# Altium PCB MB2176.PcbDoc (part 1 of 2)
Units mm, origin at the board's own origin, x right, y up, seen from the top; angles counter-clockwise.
Board outline 43 x 47 mm, 2 copper layers (Top Layer, Bottom Layer), stack 0.996 mm thick; 80 components, 70 nets, 345 pads, 549 vias.
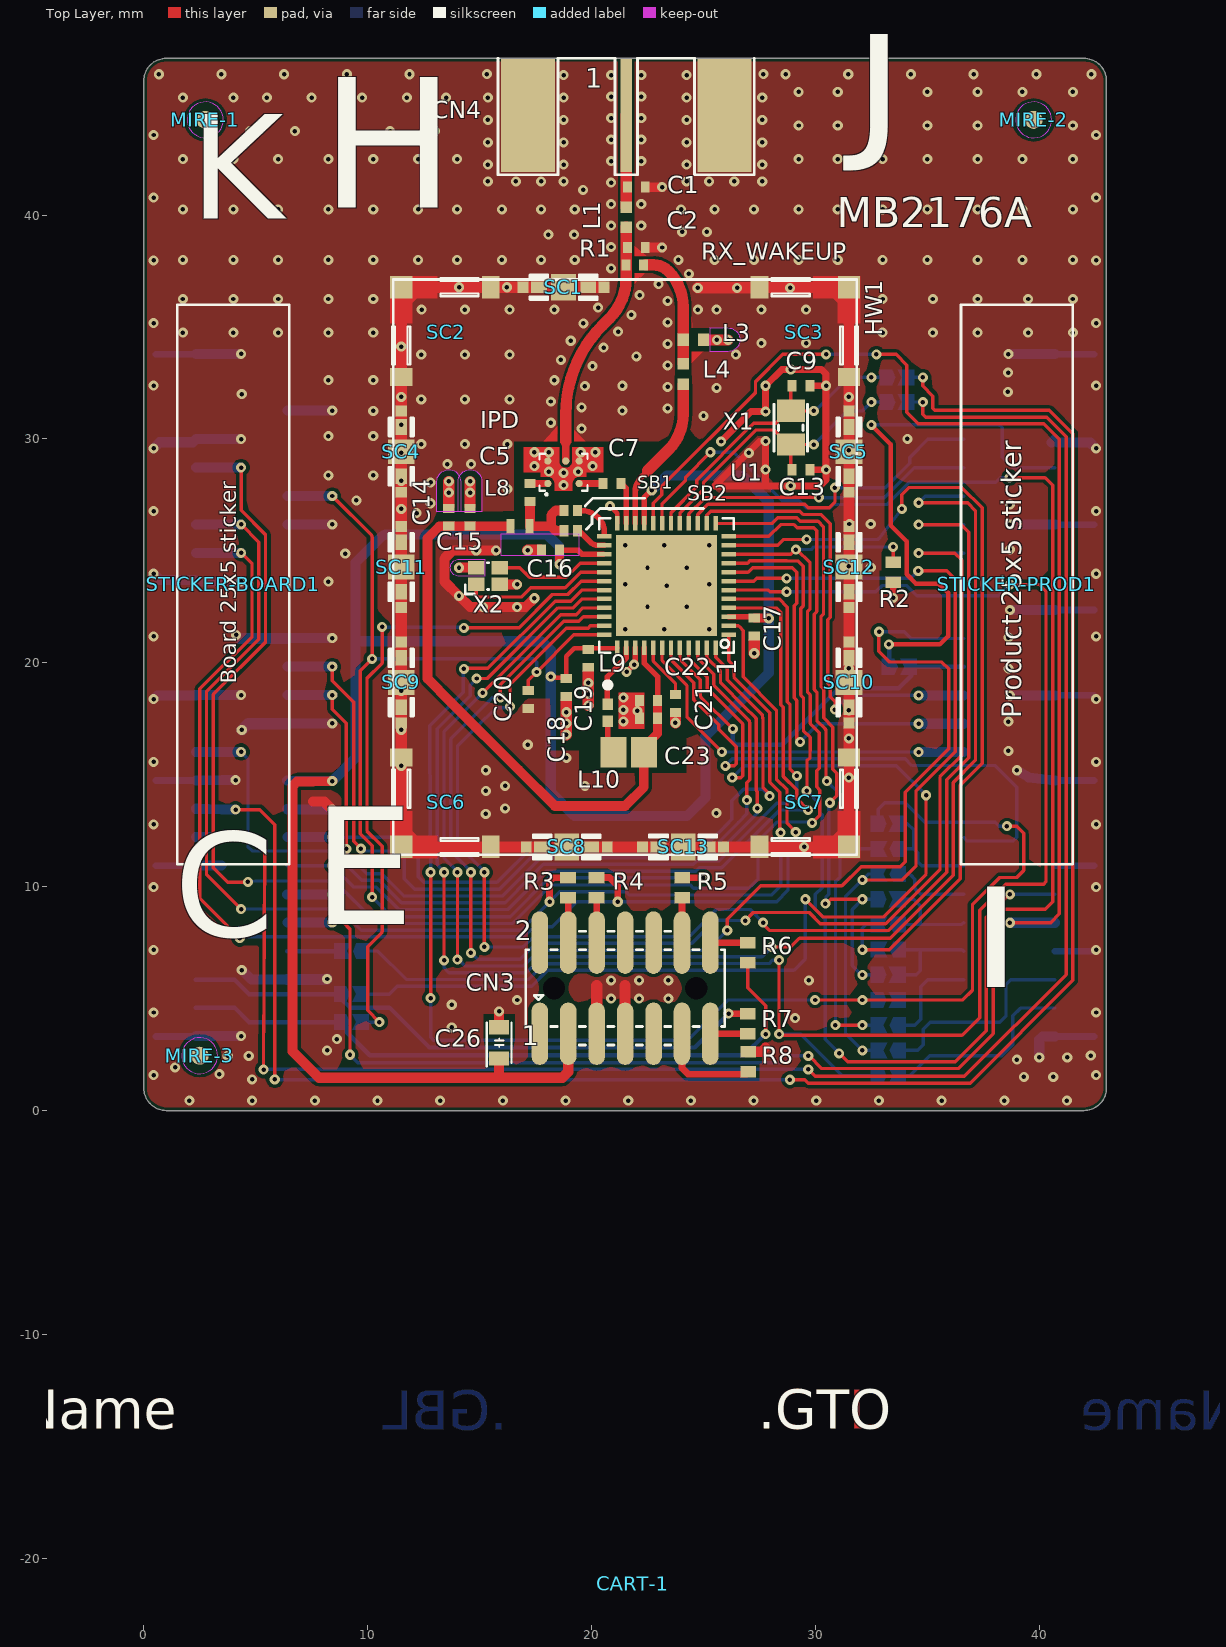
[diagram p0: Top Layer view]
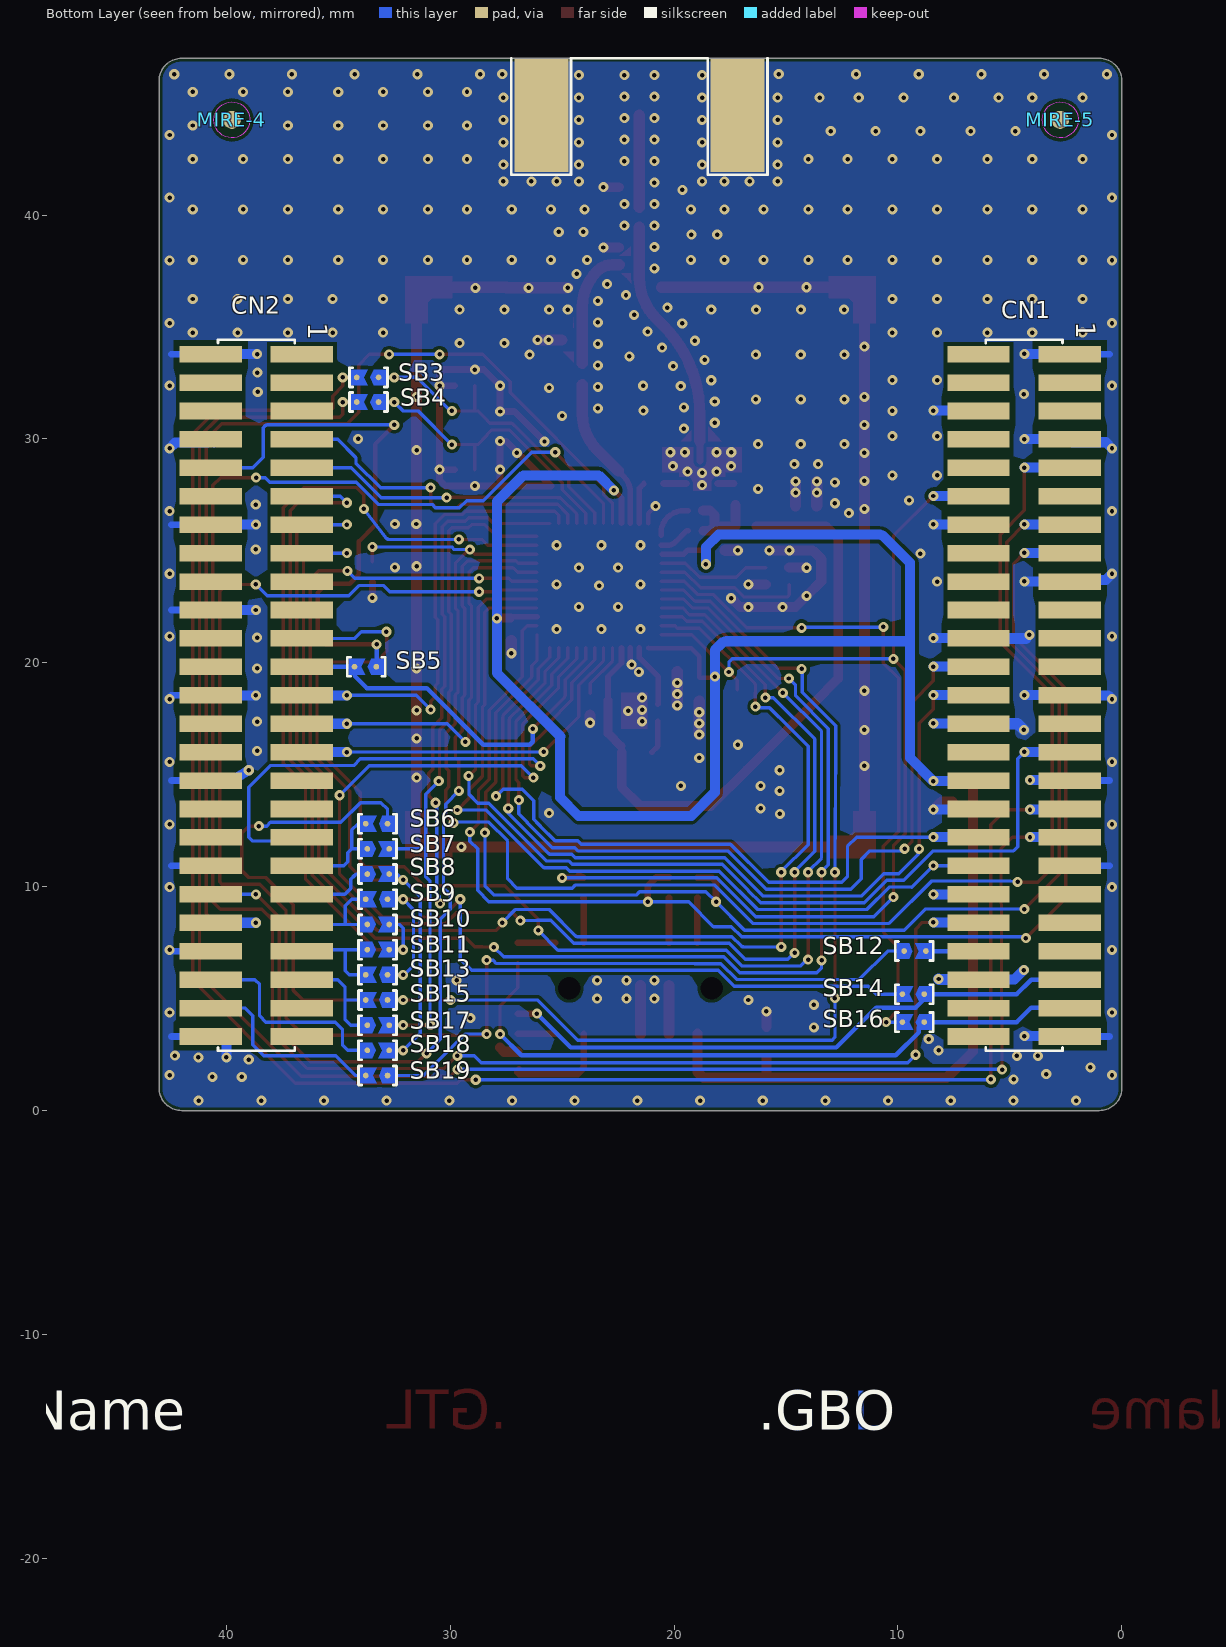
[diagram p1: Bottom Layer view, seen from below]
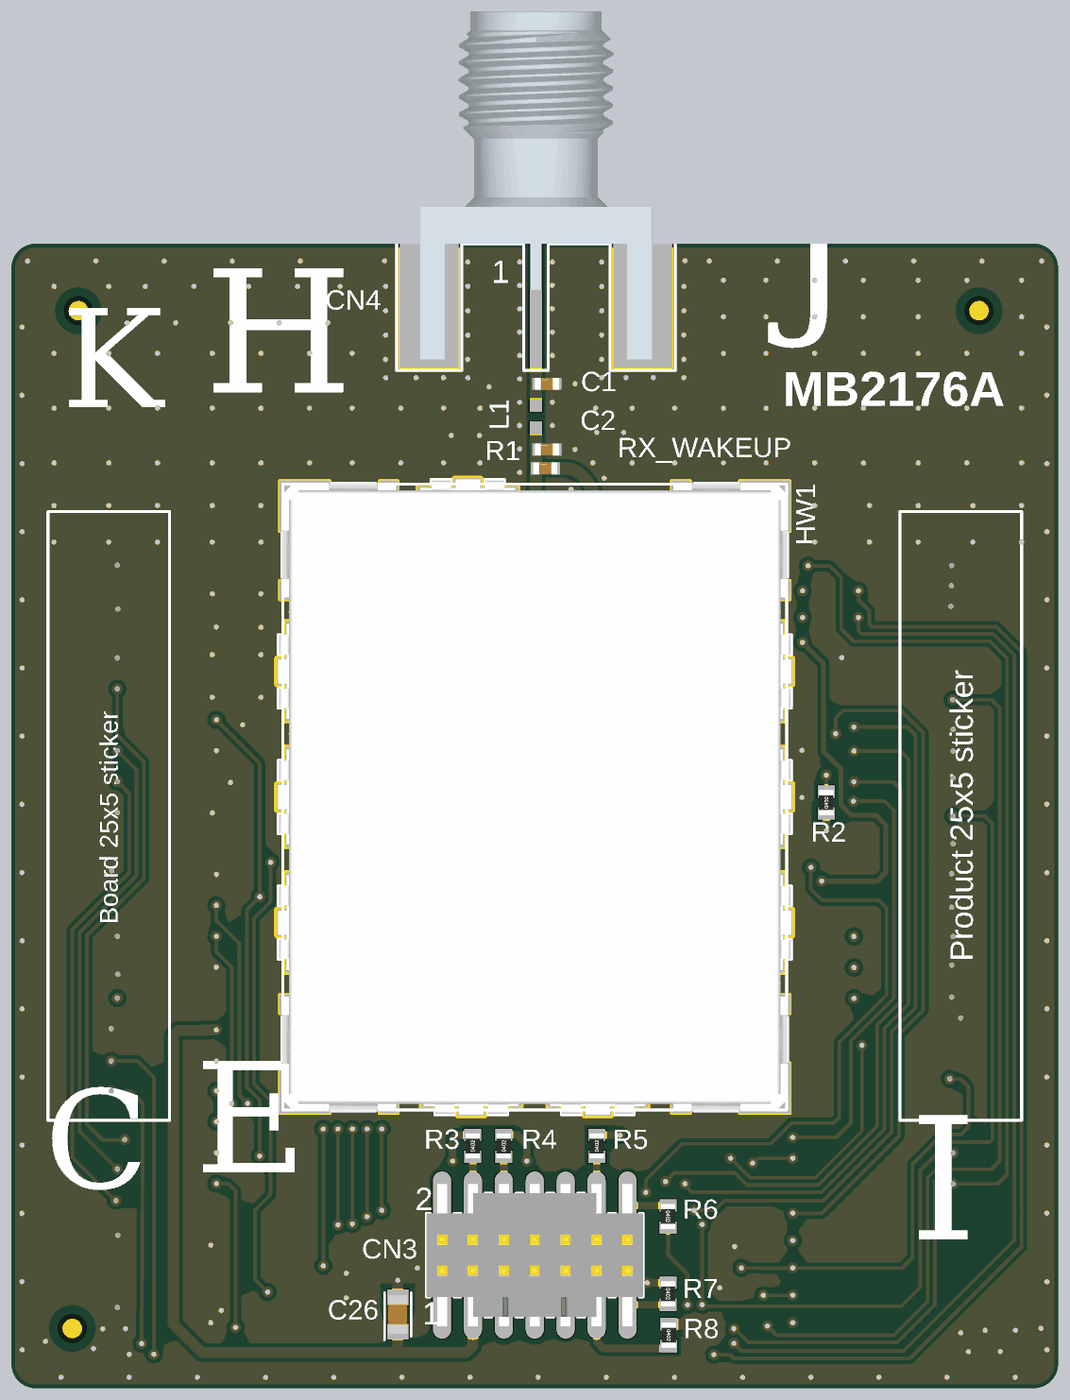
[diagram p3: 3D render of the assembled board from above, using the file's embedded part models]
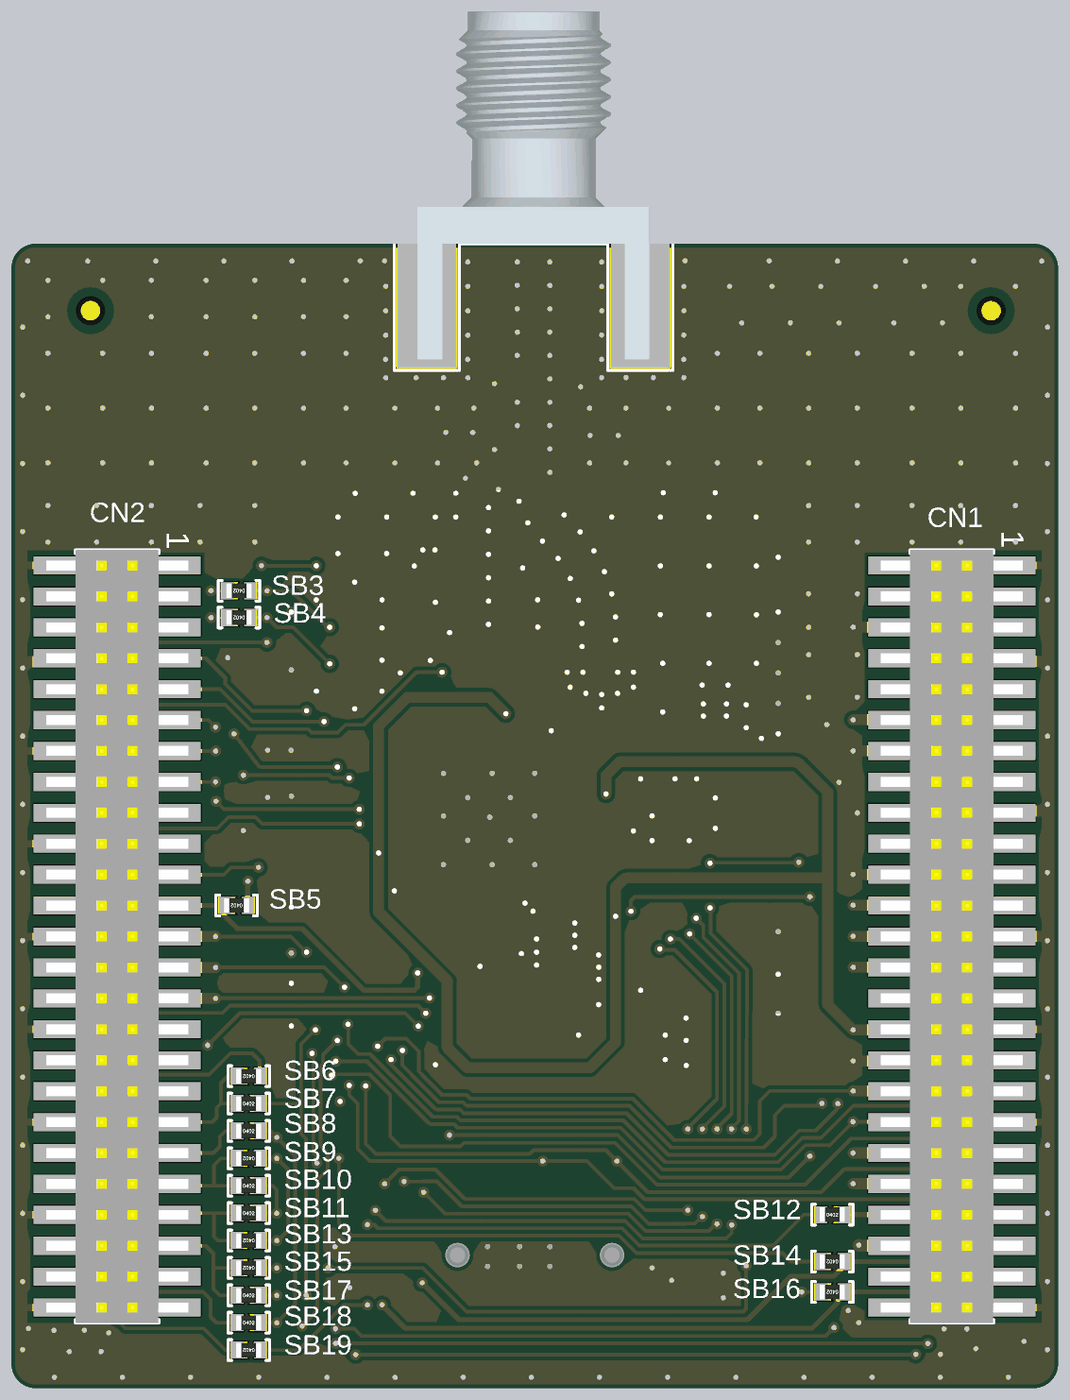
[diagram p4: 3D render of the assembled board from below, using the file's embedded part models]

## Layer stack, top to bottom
Top Solder: solder mask 0.0102, Solder Resist, Dk 3.5
Top Layer: signal copper 0.0406
Dielectric 2: core 0.9144, FR4, Dk 4.3
Bottom Layer: signal copper 0.0406
Bottom Solder: solder mask 0.0102, Solder Resist, Dk 3.5

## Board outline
0,1 ccw(c1,1) 1,0 42,0 ccw(c42,1) 43,1 43,46 ccw(c42,46) 42,47 1,47 ccw(c1,46) 0,46

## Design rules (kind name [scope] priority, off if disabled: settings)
BoardOutlineClearance [All] p1: gap=0.14 ignorepadtopadclearanceinfootprint=FALSE
Clearance [touchesRoom('RoomDefinition_3')] p1: gap=0.095 ignorepadtopadclearanceinfootprint=FALSE
Clearance Clearance_Keepout [All vs IsKeepOut] p2: gap=0.15 ignorepadtopadclearanceinfootprint=TRUE except(0: Poly-Region)
Clearance Clearance_IPD [InPadClass('IPD_PAD')] p3: gap=0.14 ignorepadtopadclearanceinfootprint=FALSE
Clearance Clearance_RF-50R [InNetClass('NC_RF-50R')] p4: gap=0.118 ignorepadtopadclearanceinfootprint=FALSE
Clearance Clearance_Default_Same-net_GND [InNet('GND')] p5: gap=0.15 ignorepadtopadclearanceinfootprint=TRUE except(0: SMDPad-Via SMDPad-Hole Via-Via Via-Region; 0.1: Arc-SMDPad Track-SMDPad Via-Hole; 0.12: SMDPad-SMDPad)
Clearance Clearance_Default_Same-net [All] p6: gap=0.15 ignorepadtopadclearanceinfootprint=TRUE except(0.1: Via-Via; 0.12: Arc-SMDPad Track-SMDPad SMDPad-SMDPad)
Clearance Clearance_Default [All] p7: gap=0.15 ignorepadtopadclearanceinfootprint=FALSE except(0.1: Arc-Via Track-Via)
ComponentClearance [All] p1: gap=0.165 collisioncheckmode=3 verticalgap=0.165 showdistances=FALSE
HoleSize [All] p1: absolutevalues=TRUE maxlimit=10 minlimit=0.025 maxpercent=80.000 minpercent=20.000
MinimumSolderMaskSliver [All] p1: minsoldermaskwidth=0.1
PlaneConnect [All] p1: planeconnectstyle=Relief reliefexpansion=0.508 reliefentries=4 reliefconductorwidth=0.21 reliefairgap=0.21
PolygonConnect PolygonConnect_CLIP [TouchesRoom('RoomDefinition')or TouchesRoom('RoomDefinition_1') or   TouchesRoom('RoomDefinition_2')  or TouchesRoom('RoomDefinition_4')  or TouchesRoom('RoomDefinition_5')    or TouchesRoom('RoomDefinition_6')] p1: connectstyle=Direct reliefconductorwidth=0.3 reliefentries=4 polygonreliefangle="90 Angle" airgapwidth=0.25
PolygonConnect PolygonConnect_Default_1 [All] p2: thpad.connectstyle=Relief thpad.reliefconductorwidth=0.3 thpad.reliefentries=4 thpad.polygonreliefangle="90 Angle" thpad.airgapwidth=0.25 smdpad.connectstyle=NoConnect smdpad.reliefconductorwidth=0.254 smdpad.reliefentries=4 smdpad.polygonreliefangle="90 Angle" smdpad.airgapwidth=0.254 via.connectstyle=Direct via.reliefconductorwidth=0.254 via.reliefentries=4 via.polygonreliefangle="90 Angle" via.airgapwidth=0.254
RoomDefinition RoomDefinition_6 [False vs False] p1: confinementstyle=ConfineIn formatcopy=TRUE lockcomponents=FALSE outline 22.217,41.754 23.136,41.754 23.136,38.308 22.217,38.308
RoomDefinition RoomDefinition_5 [False vs False] p2: confinementstyle=ConfineIn formatcopy=TRUE lockcomponents=FALSE outline 7.053,14.176 7.972,14.176 7.972,12.975 7.053,12.975
RoomDefinition RoomDefinition_4 [False vs False] p3: confinementstyle=ConfineIn formatcopy=TRUE lockcomponents=FALSE outline 16.668,18.313 18.139,18.313 18.139,17.066 16.668,17.066
RoomDefinition RoomDefinition_3 [All] p4: confinementstyle=ConfineOut formatcopy=TRUE lockcomponents=FALSE outline 17.724,29.336 19.774,29.336 19.774,27.744 17.724,27.744
RoomDefinition RoomDefinition_2 [False] p5: confinementstyle=ConfineIn formatcopy=TRUE lockcomponents=FALSE outline 27.072,12.919 27.072,10.495 16.087,10.495 16.087,12.919
RoomDefinition RoomDefinition_1 [False] p6: confinementstyle=ConfineIn formatcopy=TRUE lockcomponents=FALSE outline 32.674,15.775 30.25,15.775 30.25,28.309 32.674,28.309
RoomDefinition [False] p7: confinementstyle=ConfineIn formatcopy=TRUE lockcomponents=FALSE outline 12.674,16.465 10.25,16.465 10.25,27.45 12.674,27.45
RoutingVias RoutingVias_Default [All] p1: holewidth=0.3 width=0.6 viastyle="Through Hole" minholewidth=0.3 minwidth=0.6 maxholewidth=0.3 maxwidth=0.6 useviatemplates=TRUE viatemplateguid#1={7280008E-C29C-4D1A-93D7-D7784B042BC4} viatemplatename#1=v45h20m0mx0
SilkToSilkClearance [All] p1 off: silktosilkclearance=0.2
SilkToSolderMaskClearance [IsPad] p1 off: minsilkscreentomaskgap=0.2 clearancetoexposedcopper=TRUE
SolderMaskExpansion [All] p1: expansion=0.102 istentingtop=FALSE
ViasUnderSMD [InPadClass('PC__VIAS-IN-PAD')] p1: allowed=TRUE
Width Width_RF-50R [InNetClass('NC_RF-50R')] p1: maxlimit=0.55 minlimit=0.25 preferedwidth=0.51 impedanceprofiledriven=TRUE impedanceprofileid={AD1550EC-3D0E-4E34-9E21-FD44D1EEEC04} impedanceprofilevalue=50.000000 minimp=50.000000 maximp=50.000000 favimp=50.000000
Width Width_Default [All] p2: maxlimit=10 minlimit=0.15 preferedwidth=0.2
24 further rules are at their usual default settings.

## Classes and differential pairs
net class IPD: NetC5_1 NetC7_2
pad class PC__VIAS-IN-PAD: U1-49
net class NC_RF-50R: NetC1_2 NetC2_2 NetL3_1

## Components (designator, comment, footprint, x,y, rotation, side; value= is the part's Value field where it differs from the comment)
C1 "Capacitor" GRM155--GJM155-0_05-MFG 22,41.25 r180 top value=TBD
C2 "Capacitor" GRM155--GJM155-0_05-MFG 22,38.55 r180 top value=TBD
C5 "Capacitor" GRM155--GJM155-0_05-MFG 17.258,27.611 r90 top value=100pF
C7 "Capacitor" GRM155--GJM155-0_05-MFG 20.909,28.008 r180 top value=100pF
C9 "Capacitor" GRM155--GJM155-0_05-MFG 29.35,32.375 r180 top value=6.8pF
C13 "Capacitor" GRM155--GJM155-0_05-MFG 29.35,28.625 r180 top value=6.8pF
C14 "Capacitor" GRM155--GJM155-0_05-MFG 13.625,26.5 r90 top value=100pF
C15 "Capacitor" GRM155--GJM155-0_05-MFG 14.575,26.5 r270 top value=100nF
C16 "Capacitor" GRM155--GJM155-0_05-MFG 18.175,25.025 r0 top value=100nF
C17 "Capacitor" GRM155--GJM155-0_05-MFG 27.27,21.6 r90 top value=100nF
C18 "Capacitor" GRM155--GJM155-0_05-MFG 18.875,18.889 r90 top value=4.7uF
C19 "Capacitor" GRM155--GJM155-0_05-MFG 19.857,20.2 r90 top value=TBD
C20 "Capacitor" GRM155--GJM155-0_05-MFG 17.172,18.352 r90 top value=100nF
C21 "Capacitor" GRM155--GJM155-0_05-MFG 23.75,18.175 r90 top value=220nF
C22 "Capacitor" GRM155--GJM155-0_05-MFG 22.55,18.321 r0 top value=4.7uF
C23 "Capacitor" GRM155--GJM155-0_05-MFG 22.55,17.525 r180 top value=100nF
C26 "Capacitor" C0603 15.875,3.025 r270 top value=1uF
CART-1 "Comment" Sheetbox_4L2S -23.25,-26.5 r0 top
CN1 "FTSH-125-02-L-DV" CON_SAMTEC_FTSH-125-02-L-DV_INV 4.366,18.548 r270 bottom locked value="Header 25x2"
CN2 "FTSH-125-02-L-DV" CON_SAMTEC_FTSH-125-02-L-DV_INV 38.656,18.548 r270 bottom locked value="Header 25x2"
CN3 "Header 7x2" CON_SAMTEC_FTSH-107-01-L-DV-K-A 21.5,5.465 r0 top locked
CN4 "mmcx" CON_SMA-RF_CINCH_142-0701-851 21.55,47 r0 top
HW1 "S02-20150300" SHIELD_HARWIN_S02-25200300_20X25_H3 21.5,24.275 r0 top locked value=S02-25200300R
IPD "STM32WL33_IPD" STM32WL33_IPD 19.674,27.786 r90 top
L1 "Inductor" L0402#1 21.55,39.9 r90 top value=0R
L3 "Inductor" L0402#2 24.55,34.425 r0 top value=TBD
L4 "Inductor" L0402#1 24.1,32.9 r90 top value=TBD
L8 "Inductor" LQW15AN_00-W0_6-0_1-MFG 16.8,26.1 r0 top value=TBD
L9 "Inductor" LQG15HH_02-IPC_C 20.725,17.773 r270 top value=TBD
L10 "Inductor" LQM21FN_70-IPC_C 21.663,16.008 r180 top value=10µH
MIRE-1 "Comment" MIRE_PLACE_SMD_0P8MM 2.75,44.25 r0 top
MIRE-2 "Comment" MIRE_PLACE_SMD_0P8MM 39.75,44.25 r0 top
MIRE-3 "Comment" MIRE_PLACE_SMD_0P8MM 2.5,2.45 r0 top
MIRE-4 "Comment" MIRE_PLACE_SMD_0P8MM 39.75,44.25 r180 bottom
MIRE-5 "Comment" MIRE_PLACE_SMD_0P8MM 2.75,44.25 r180 bottom
R1 "Resistor" GRM155--GJM155-0_05-MFG 21.93,37.775 r180 top value=0
R2 "Resistor" R0402 33.475,24.05 r90 top value=100K
R3 "Resistor" R0402 18.95,9.95 r90 top value=47R
R4 "Resistor" R0402 20.225,9.95 r90 top value=47R
R5 "Resistor" R0402 24.05,9.95 r90 top value=47R
R6 "Resistor" R0402 26.975,7.05 r270 top value=47R
R7 "Resistor" R0402 26.975,3.875 r270 top value=47R
R8 "Resistor" R0402 27.003,2.175 r270 top value=47R
SB1 "SB_ON" SOLDER-BRIDGE_R0201_0R 19.075,26.8 r180 top value=0R
SB2 "SB_ON" SOLDER-BRIDGE_R0201_0R 19.075,25.9 r180 top value=0R
SB3 "SB_ON" SOLDER-BRIDGE_R0402-0R 33.65,32.747 r0 bottom
SB4 "SB_ON" SOLDER-BRIDGE_R0402-0R 33.65,31.647 r0 bottom
SB5 "SB_ON" SOLDER-BRIDGE_R0402-0R 33.75,19.825 r0 bottom
SB6 "SB_ON" SOLDER-BRIDGE_R0402-0R 33.25,12.812 r0 bottom
SB7 "SB_ON" SOLDER-BRIDGE_R0402-0R 33.25,11.688 r180 bottom
SB8 "SB_ON" SOLDER-BRIDGE_R0402-0R 33.25,10.563 r180 bottom
SB9 "SB_ON" SOLDER-BRIDGE_R0402-0R 33.25,9.437 r0 bottom
SB10 "SB_ON" SOLDER-BRIDGE_R0402-0R 33.25,8.313 r180 bottom
SB11 "SB_ON" SOLDER-BRIDGE_R0402-0R 33.25,7.187 r180 bottom
SB12 "SB_ON" SOLDER-BRIDGE_R0402-0R 9.275,7.125 r180 bottom
SB13 "SB_ON" SOLDER-BRIDGE_R0402-0R 33.25,6.062 r0 bottom
SB14 "SB_ON" SOLDER-BRIDGE_R0402-0R 9.275,5.2 r0 bottom
SB15 "SB_ON" SOLDER-BRIDGE_R0402-0R 33.25,4.938 r0 bottom
SB16 "SB_ON" SOLDER-BRIDGE_R0402-0R 9.275,3.95 r0 bottom
SB17 "SB_ON" SOLDER-BRIDGE_R0402-0R 33.25,3.812 r180 bottom
SB18 "SB_ON" SOLDER-BRIDGE_R0402-0R 33.25,2.688 r180 bottom
SB19 "SB_ON" SOLDER-BRIDGE_R0402-0R 33.25,1.562 r0 bottom
SC1 "Shield-clip_S0951-46R" CLIP_HARWIN_S0951-46R 18.75,36.775 r180 top value=S0951-46R
SC2 "Shield-clip_S0951-46R" CLIP_HARWIN_S0981-46R 11.5,36.775 r180 top value=S0981-46R
SC3 "Shield-clip_S0951-46R" CLIP_HARWIN_S0981-46R 31.5,36.775 r90 top value=S0981-46R
SC4 "Shield-clip_S0951-46R" CLIP_HARWIN_S0951-46R 11.5,29.433 r90 top value=S0951-46R
SC5 "Shield-clip_S0951-46R" CLIP_HARWIN_S0951-46R 31.5,29.433 r90 top value=S0951-46R
SC6 "Shield-clip_S0951-46R" CLIP_HARWIN_S0981-46R 11.5,11.775 r270 top value=S0981-46R
SC7 "Shield-clip_S0951-46R" CLIP_HARWIN_S0981-46R 31.5,11.775 r0 top value=S0981-46R
SC8 "Shield-clip_S0951-46R" CLIP_HARWIN_S0951-46R 18.89,11.774 r180 top value=S0951-46R
SC9 "Shield-clip_S0951-46R" CLIP_HARWIN_S0951-46R 11.5,19.12 r90 top value=S0951-46R
SC10 "Shield-clip_S0951-46R" CLIP_HARWIN_S0951-46R 31.5,19.12 r270 top value=S0951-46R
SC11 "Shield-clip_S0951-46R" CLIP_HARWIN_S0951-46R 11.5,24.278 r90 top value=S0951-46R
SC12 "Shield-clip_S0951-46R" CLIP_HARWIN_S0951-46R 31.5,24.278 r270 top value=S0951-46R
SC13 "Shield-clip_S0951-46R" CLIP_HARWIN_S0951-46R 24.09,11.775 r0 top value=S0951-46R
STICKER-BOARD1 "Comment" STICKER_BOARD_25X5 4,23.5 r90 top
STICKER-PROD1 "Comment" STICKER_PRODUCT_25X5 39,23.5 r90 top
U1 "STM32WL33" ICC_QFN48-EPAD-4P5X4P5_6X6_P040 23.35,23.45 r180 top
X1 "XTAL_2_PINS" CRY_NX2012SA_2P 28.9,30.5 r90 top value=32.768kHz
X2 "XTAL_4_PINS" CRY_NX1612SA_4P 15.38,23.875 r0 top locked value=48MHz

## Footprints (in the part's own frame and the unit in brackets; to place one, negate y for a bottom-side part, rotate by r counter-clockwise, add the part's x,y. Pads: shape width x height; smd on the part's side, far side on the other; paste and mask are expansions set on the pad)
C0603 [mm]
  rect 0.64x0.89 smd mask+0.05: 1(-0.7,0) 2(0.7,0)
  silkscreen extent -0.9,-0.55 1.05,0.55, body extent -0.9,-0.5 0.9,0.5, height 1.4
CLIP_HARWIN_S0951-46R [mm] "MCD-01587_CLIP-X1"
  rect 0.48x0.5 smd mask+0.1: 1(-1.81,0) 1(1.81,0)
  rect 0.7x0.5 smd mask+0.1: 1(-1.1,0) 1(1.1,0)
  rect 1.1x1.2 smd mask+0.1: 1(0,0)
  silkscreen extent -1.5,-0.55 1.5,0.55, body extent -2.05,-0.65 2.05,0.65, height 1.28
CLIP_HARWIN_S0981-46R [mm] "MCD-02164"
  rect 0.8x1 smd mask+0.05: 1(-4,0)
  rect 1x0.8 smd mask+0.05: 1(0,4)
  rect 1x1 smd mask+0.05: 1(0,0)
  Top Layer region: -1.6,-0.5 0.5,-0.5 0.5,1.6 -0.5,1.6 -0.5,0.7 -0.7,0.5 -1.6,0.5
  silkscreen extent -3.45,-0.4 0.4,3.45, body extent -4.3,-0.46 0.46,4.3, height 1.4
CON_SAMTEC_FTSH-107-01-L-DV-K-A [mm] "MCD-01959"
  oval 0.74x2.79 smd mask+0.05: 1(-3.81,-2.035) 2(-3.81,2.035) 3(-2.54,-2.035) 4(-2.54,2.035) 5(-1.27,-2.035) 6(-1.27,2.035) 7(0,-2.035) 8(0,2.035) 9(1.27,-2.035) 10(1.27,2.035) 11(2.54,-2.035) 12(2.54,2.035) 13(3.81,-2.035) 14(3.81,2.035)
  round 0 hole 1 unplated paste-2539.97 mask+0.05: NPTH1(-3.175,0) NPTH2(3.175,0)
  silkscreen extent -4.44,-2.54 4.44,2.54, body extent -4.44,-2.92 4.45,2.92, height 6.12
CON_SAMTEC_FTSH-125-02-L-DV_INV [mm]
  rect 0.74x2.79 smd mask+0.05: 1(-15.24,2.035) 2(-15.24,-2.035) 3(-13.97,2.035) 4(-13.97,-2.035) 5(-12.7,2.035) 6(-12.7,-2.035) 7(-11.43,2.035) 8(-11.43,-2.035) 9(-10.16,2.035) 10(-10.16,-2.035) 11(-8.89,2.035) 12(-8.89,-2.035) 13(-7.62,2.035) 14(-7.62,-2.035) 15(-6.35,2.035) 16(-6.35,-2.035) 17(-5.08,2.035) 18(-5.08,-2.035) 19(-3.81,2.035) 20(-3.81,-2.035) 21(-2.54,2.035) 22(-2.54,-2.035) 23(-1.27,2.035) 24(-1.27,-2.035) 25(0,2.035) 26(0,-2.035) 27(1.27,2.035) 28(1.27,-2.035) 29(2.54,2.035) 30(2.54,-2.035) 31(3.81,2.035) 32(3.81,-2.035) 33(5.08,2.035) 34(5.08,-2.035) 35(6.35,2.035) 36(6.35,-2.035) 37(7.62,2.035) 38(7.62,-2.035) 39(8.89,2.035) 40(8.89,-2.035) 41(10.16,2.035) 42(10.16,-2.035) 43(11.43,2.035) 44(11.43,-2.035) 45(12.7,2.035) 46(12.7,-2.035) 47(13.97,2.035) 48(13.97,-2.035) 49(15.24,2.035) 50(15.24,-2.035)
  silkscreen extent -15.88,-1.71 15.88,1.71, body extent -15.87,-2.92 15.88,2.92, height 4.82
CON_SMA-RF_CINCH_142-0701-851 [mil] "MCD-02072"
  rect 20.08x200 smd mask+1.97: 1(0,-100)
  rect 95x200 smd mask+1.97: 2(172.48,-100) 3(-172.48,-100)
  rect 95x200 smd far side mask+1.97: 4(-172.48,-100) 5(172.48,-100)
  silkscreen extent -225,-205 225,0, body extent -189,-187 189,376, height 161
CRY_NX1612SA_4P [mm] "MCD-02262"
  rect 0.75x0.6 smd mask+0.038: 1(-0.525,-0.375) 2(0.525,-0.375) 3(0.525,0.375) 4(-0.525,0.375)
  silkscreen extent -1.02,-0.8 0.03,0.6, body extent -0.8,-0.6 0.8,0.6, height 0.31
CRY_NX2012SA_2P [mm]
  rect 1x1.25 smd mask+0.05: 1(-0.75,0) 2(0.75,0)
  silkscreen extent -1.05,-0.75 1.05,0.75, body extent -1.05,-0.63 1.05,0.63, height 0.6
GRM155--GJM155-0_05-MFG [mm]
  rect 0.4x0.5 smd paste+0 mask+0: 1(-0.4,0) 2(0.4,0)
  body extent -0.7,-0.38 0.7,0.38, height 0.25
ICC_QFN48-EPAD-4P5X4P5_6X6_P040 [mm] "MCD-03488"
  rect 0.65x0.2 smd mask+0.05: 1(-2.775,2.2) 2(-2.775,1.8) 3(-2.775,1.4) 4(-2.775,1) 5(-2.775,0.6) 6(-2.775,0.2) 7(-2.775,-0.2) 8(-2.775,-0.6) 9(-2.775,-1) 10(-2.775,-1.4) 11(-2.775,-1.8) 12(-2.775,-2.2) 25(2.775,-2.2) 26(2.775,-1.8) 27(2.775,-1.4) 28(2.775,-1) 29(2.775,-0.6) 30(2.775,-0.2) 31(2.775,0.2) 32(2.775,0.6) 33(2.775,1) 34(2.775,1.4) 35(2.775,1.8) 36(2.775,2.2)
  rect 0.2x0.65 smd mask+0.05: 13(-2.2,-2.775) 14(-1.8,-2.775) 15(-1.4,-2.775) 16(-1,-2.775) 17(-0.6,-2.775) 18(-0.2,-2.775) 19(0.2,-2.775) 20(0.6,-2.775) 21(1,-2.775) 22(1.4,-2.775) 23(1.8,-2.775) 24(2.2,-2.775) 37(2.2,2.775) 38(1.8,2.775) 39(1.4,2.775) 40(1,2.775) 41(0.6,2.775) 42(0.2,2.775) 43(-0.2,2.775) 44(-0.6,2.775) 45(-1,2.775) 46(-1.4,2.775) 47(-1.8,2.775) 48(-2.2,2.775)
  rect 4.5x4.5 smd mask+0.05: 49(0,0)
  silkscreen extent -3,-3 3,3, body extent -3,-3 3,3, height 0.91
L0402#1 [mm]
  rect 0.51x0.51 smd mask+0.05: 1(-0.45,0) 2(0.45,0)
  body extent -0.5,-0.3 0.5,0.3, height 0.51
L0402#2 [mm]
  rect 0.51x0.56 smd mask+0.05: 1(-0.45,0) 2(0.45,0)
  body extent -0.5,-0.3 0.5,0.3, height 0.51
LQG15HH_02-IPC_C [mm]
  rect 0.515x0.472 smd paste+0 mask+0: 1(-0.379,0) 2(0.379,0)
  silkscreen extent -1.36,-0.12 -1.11,0.13, body extent -0.74,-0.38 0.74,0.38, height 0.25
LQM21FN_70-IPC_C [mm]
  rect 1.154x1.356 smd paste+0 mask+0: 1(-0.676,0) 2(0.676,0)
  body extent -1.35,-0.82 1.35,0.82, height 0.25
LQW15AN_00-W0_6-0_1-MFG [mm]
  rect 0.35x0.65 smd paste+0 mask+0: 1(-0.425,0) 2(0.425,0)
  body extent -0.7,-0.45 0.7,0.45, height 0.25
MIRE_PLACE_SMD_0P8MM [mm]
  round 0.8 smd paste-10 mask+0.2: 1(0,0)
  Top Layer keep-out circle w0.01: c0,0 r0.804
R0402 [mm]
  rect 0.51x0.7 smd mask+0.05: 1(-0.45,0) 2(0.45,0)
  body extent -0.52,-0.3 0.52,0.3, height 0.4
Sheetbox_4L2S [mil] "Sheetbox 4 layers / 2 silkscreens"
  round 20 on Mech16: 1(813.78,210.69) 1(2736.9,210.69)
SHIELD_HARWIN_S02-25200300_20X25_H3 [mm] "MCD-03503"
  silkscreen extent -10.35,-12.85 10.35,12.85, body extent -10.1,-12.6 10.1,12.6, height 3.2
SOLDER-BRIDGE_R0201_0R [mm] "MCD-03219"
  rect 0.4x0.5 smd mask+0.05: 1(-0.3,0) 2(0.3,0)
  body extent -0.32,-0.17 0.32,0.17, height 0.26
SOLDER-BRIDGE_R0402-0R [mil] "MCD-01619"
  round 10 smd paste-393.7: 1(-17.72,0) 2(20.67,0)
  Top Layer region: 1.48,13.78 8.37,0 1.48,-13.78 30.51,-13.78 30.51,13.78
  Top Layer region: -30.51,-13.78 -30.51,13.78 -8.86,13.78 -2.95,0 -8.86,-13.78
  silkscreen extent -33,-17 33,17, body extent -20,-12 20,12, height 14
STICKER_BOARD_25X5 [mm] "Sticker to mention board reference + serial number"
  silkscreen extent -12.5,-2.5 12.5,2.5
STICKER_PRODUCT_25X5 [mm] "Sticker to mention board CPN code"
  silkscreen extent -12.5,-2.5 12.5,2.5
STM32WL33_IPD [mm]
  round 0.32 smd paste-0.05 mask-0.05: 1(0.225,1.625) 2(0.225,0.225) 3(1.225,0.225) 4(1.225,0.825) 5(1.225,1.625)
  silkscreen extent -0.32,-0.15 1.55,2, body extent 0,0 1.45,1.85, height 0.3

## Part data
C1 C2: library part MCD-01600, "Capacitor, MLCC, 1pF, 50V, NPO, +/-0.1pF, 0402, T=0.5mm", Manufacturer=YAGEO, Manufacturer_Part_Number=TBD, Package=0402
C5 C7 C14: library part MCD-03446, "Capacitor, MLCC, 100pF, 50V, COG, 1%, 0402, T=0.5mm", Manufacturer=MURATA, Manufacturer_Part_Number=GCM1555C1H101FA16, Package=0402
C9 C13: library part MCD-03452, "Capacitor, MLCC, 6.8pF, ±0.05pF, C0G, 50V, 0402, T=0.5mm", Manufacturer=MURATA, Manufacturer_Part_Number=GJM1555C1H6R8WB01, Package=0402
C15 C23: library part MCD-03442, "Capacitor, MLCC, 100nF, ±10%, X7R, 25V, 0402, T=0.5mm", Manufacturer=MURATA, Manufacturer_Part_Number=GRM155R71E104KE14D, Package=0402
C16 C17: library part MCD-03442, "Capacitor, MLCC, 100nF, +/-10%, X7R, 25V, 0402, T=0.5mm", Manufacturer=MURATA, Manufacturer_Part_Number=GRM155R71E104KE14D, Package=0402
C18 C22: library part MCD-03431, "Capacitor, MLCC, 4.7uF, X5R, 10 V, 0402, ± 20%, T=0.5mm", Manufacturer=MURATA, Manufacturer_Part_Number=GRM155R61A475MEAAD, Package=0402
C19: library part MCD-03442, "Capacitor, MLCC, 100nF, ±10%, X7R, 25V, 0402, T=0.5mm", Manufacturer=MURATA, Manufacturer_Part_Number=TBD, Package=0402
C20: library part MCD-00006, "Capacitor, MLCC, 100nF, 16V, X7R, +/-10%, 0402, T=0.5mm", Alternate_Manufacturer=MURATA, Alternate_Manufacturer_Part_Number=GCM155R71C104KA55D, Manufacturer=YAGEO, Manufacturer_Part_Number=CC0402KRX7R7BB104, Package=C0402
C21: library part MCD-03077, "Capacitor, MLCC, 220nF, 35V, X6S, +/-10%, 0402, T=0.5mm", Manufacturer=MURATA, Manufacturer_Part_Number=GRM155C8YA224KE01D, Package=0402
C26: library part MCD-00010, "Capacitor, MLCC, 1uF, 16V, X5R, 10%, 0603, T=0,8mm", Manufacturer=YAGEO, Manufacturer_Part_Number=CC0603KRX5R7BB105, Package=C0603
CART-1: library part MCD-00279
CN1 CN2: library part MCD-02746, "Header, 25x2, 12.7mm, VR, SMD, T=4.83mm", Manufacturer=SAMTEC
CN3: library part MCD-01531, "Header, 7x2, 1.27mm, VR, T=5.97mm, FTSH series STDC14 without Alignment Pin", Manufacturer=SAMTEC, Manufacturer_Part_Number=FTSH-107-01-L-DV-K
CN4: library part MCD-02072, "Jack_SMA, VR, PCB edge, 50R, T=7.92mm", Alternate_Manufacturer=N/A, Manufacturer=CINCH, Manufacturer_Part_Number=142-0711-881
HW1: library part MCD-03503, "RFI shield CAN, 25x20x3mm", Manufacturer=HARWIN, Manufacturer_Part_Number=S02-25200300R, Package=25x20x3mm
IPD: "IPD for STM32WL3", Manufacturer=STMICROELECTRONICS, Package=CSP
L1: library part MCD-01937, "Resistor, 0R, 0402, +/-5%, 1/16W", Manufacturer=YAGEO, Manufacturer_Part_Number=RC0402JR-070RL, Package=0402
L3: library part MCD-03462, "Inductor, MLCC, 5.6nH, ±0.3nH, 650mA, 180mR, 0402, T=0.5mm", Manufacturer=MURATA, Manufacturer_Part_Number=TBD, Package=0402
L4: library part MCD-03461, "Inductor, 6.8nH, +/-3%, 0.6A, 220mR, 0402, T=0.5mm", Manufacturer=MURATA, Manufacturer_Part_Number=TBD, Package=0402
L8: library part MCD-03456, "Inductor, Wire-wound, 12nHH, ±2%, 500mA, 1405mR, 0402, T=0.5mm", Manufacturer=MURATA, Manufacturer_Part_Number=TBD, Package=0402
L9: library part MCD-03453, "Inductor, MLCC, 100nH, ±5%, 200mA, 1.25R, 0402, T=0.5mm", Manufacturer=MURATA, Manufacturer_Part_Number=LQG15HSR10J02, Package=0402
L10: library part MCD-03557, "Inductor, 10uH, +/-20%, 100mA, 1R36, 0805, T=0.8mm", Manufacturer=MURATA, Manufacturer_Part_Number=LQM21FN100M80, Package=0805
R1: library part MCD-03301, "0 ohm resistor", Manufacturer=YAGEO, Manufacturer_Part_Number=RT0402FRE07100KL, Package=0402
R2: library part MCD-03301, "Resistor, 100K, 0402, +/-1%, 1/16W", Manufacturer=YAGEO, Manufacturer_Part_Number=RT0402FRE07100KL, Package=0402
R3 R4 R5 R6 R7 R8: library part MCD-00481, "Resistor,47R,0402,1%,1/16W", Manufacturer=YAGEO, Manufacturer_Part_Number=RC0402FR-0747RL, Package=R0402
SB1 SB2: library part MCD-03219, "Resistor, 0R, 0201, Solder Bridge ON , 1/20W,", Manufacturer=YAGEO, Manufacturer_Part_Number=RC0201JR-070RL, Package=SB0201
SB3 SB4 SB5 SB6 SB7 SB8 SB9 SB10 SB11 SB12 SB13 SB14 SB15 SB16 SB17 SB18 SB19: library part MCD-01618, "Solder Bridge 0402 ON", Manufacturer=YAGEO, Manufacturer_Part_Number=RC0402JR-070RL, Package=SB0402
SC1 SC4 SC5 SC8: library part MCD-01587, "shield clip Harwin S0951-46R to fix RF shielded cavity", Manufacturer=HARWIN, Manufacturer_Part_Number=S0951-46R
SC2 SC3 SC6 SC7: library part MCD-02164, "shield clip Harwin S0981-46R to fix RF shielded cavity - SMT RFI Shield Clip, Corner (T+R)", Manufacturer=HARWIN, Manufacturer_Part_Number=S0981-46R
SC9 SC10 SC11 SC12 SC13: library part MCD-01587, "RFI shield clip mini TIN SMD", Manufacturer=HARWIN, Manufacturer_Part_Number=S0951-46R, Package=1.1x3.9mm
U1: library part MCD-03488, "IC, Programmable Sub-1GHz wireless SoC", Manufacturer=STMICROELECTRONICS, Package=QFN48
X1: library part MCD-01445, "Crystal, 32.768kHz, 7pF, +/-20ppm, 80K, 2.05x1.2mm", Manufacturer=NDK, Manufacturer_Part_Number=NX2012SA-32.768KHZ-EXS00A-MU00389, Package=2.05x1.2mm
X2: library part MCD-03559, "Crystal, 48MHz, 8pF, +/-10 ppm, 22R, 1.6x1.2mm", Manufacturer=NDK, Manufacturer_Part_Number="NX1612SA-48.000 MHz-EXS00A-CS12140", Package=1.6*1.2mm

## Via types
v1: diameter 0.45, hole 0.2, Top Layer to Bottom Layer, tented both sides, 549 vias

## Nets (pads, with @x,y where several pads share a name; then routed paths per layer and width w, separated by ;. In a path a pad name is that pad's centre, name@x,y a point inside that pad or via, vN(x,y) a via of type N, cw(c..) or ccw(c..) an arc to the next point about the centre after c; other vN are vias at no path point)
GND: C1.1 C2.1 C9.1 C13.1 C14.2 C15.1 C16.1 C17.1 C18.1 C19.1 C20.1 C21.1 C22.1 C23.2 C26.1 CN1.1 CN1.6 CN1.7 CN1.14 CN1.17 CN1.22 CN1.25 CN1.28 CN1.31 CN1.34 CN1.37 CN1.40 CN1.46 CN1.49 CN2.2 CN2.8 CN2.14 CN2.20 CN2.26 CN2.32 CN2.38 CN2.44 CN2.50 CN3.5 CN3.7 CN4.2 CN4.3 CN4.4 CN4.5 IPD.3 IPD.5 L3.2 R2.1 R8.1 SC1.1 SC2.1 SC3.1 SC4.1 SC5.1 SC6.1 SC7.1 SC8.1 SC9.1 SC10.1 SC11.1 SC12.1 SC13.1 U1.24 U1.39 U1.49 X2.2 X2.4 | length 211.7
  Top Layer w0.2: v1(20.825,27) 21.15,26.675 U1.24@21.15,26.225
  Top Layer w0.25: v1(21.571,19.59) v1(21.9,19.919) ; v1@21.95,20.023 21.95,20.202 U1.39@21.95,20.675
  Top Layer w0.3: v1@16.675,23.5 v1(16.68,23.505) ; v1(25.787,29.884) 27.128,31.225 27.34,31.225 v1(27.775,31.225) v1(27.775,32.375) 28.5,33.1 v1(28.9,33.1) 30.275,33.1 30.475,32.9 v1(30.475,32.375) ; C13.1@29.8,28.625 v1(30.475,28.625) ; C9.1@29.8,32.375 v1(30.475,32.375) ; v1(33.475,22.895) R2.1@33.475,23.6 ; 27.7,27.9 27.775,27.975 v1(27.775,28.625) v1(27.775,29.9) 27.766,29.891 27.491,29.891 25.5,27.9 27.7,27.9 ; 27.7,27.9 v1(28.9,27.9) 30.214,27.9 30.475,28.161 v1(30.475,28.625) ; v1(30.475,28.625) v1(30.475,32.375)
  Top Layer w0.43: C2.1@22.45,38.55 v1(23.155,38.55) ; C1.1@22.45,41.25 v1(23.155,41.25)
  Top Layer w0.45: 7.557,13.797 8.06,13.797 v1(8.42,13.437) ; v1(14.08,24.245) 14.085,24.25 X2.4@14.855,24.25 ; v1(15.74,25.025) v1(14.85,25.025) 13.809,25.025 13.425,24.642 13.425,23.642 v1(14.08,22.988) 14.58,22.488 v1(15.155,22.488) v1(16.68,22.488) 17.053,22.488 v1(17.449,22.883) ; C26.1@15.875,3.725 v1(15.875,4.43) ; X2.2@15.905,23.5 v1@16.675,23.5 ; R8.1@27.003,2.625 27.587,2.625 27.775,2.812
  Top Layer w0.5: C14.2@13.625,27 v1(13.625,27.6) v1(13.625,28.1) ; C15.1@14.575,27 v1(14.575,27.6) v1(14.575,28.1) ; SC1.1@16.94,36.775 v1(16.22,36.775) SC2.1@15.5,36.775 SC2.1@11.5,36.775 v1(11.5,34.125) SC2.1@11.5,32.775 SC4.1@11.5,31.243 SC4.1@11.5,30.533 SC4.1@11.5,29.433 v1(11.5,29.375) SC4.1@11.5,28.333 SC4.1@11.5,27.623 SC11.1@11.5,26.088 SC11.1@11.5,25.378 SC11.1@11.5,24.278 SC11.1@11.5,23.178 SC11.1@11.5,22.468 SC9.1@11.5,20.93 SC9.1@11.5,20.22 SC9.1@11.5,19.12 SC9.1@11.5,18.02 SC9.1@11.5,17.31 SC6.1@11.5,15.775 v1(11.5,15.395) SC6.1@11.5,11.775 SC6.1@15.5,11.775 19.69,11.775 23.31,11.775 SC7.1@27.5,11.775 v1(29.5,11.775) SC7.1@31.5,11.775 v1(31.5,14.875) SC7.1@31.5,15.775 v1(31.5,16.625) v1(31.5,17.875) v1(31.5,19.75) 31.5,22.464 SC5.1@31.5,27.623 SC5.1@31.5,28.333 SC5.1@31.5,29.433 SC5.1@31.5,30.533 SC5.1@31.5,31.243 SC3.1@31.5,32.775 SC3.1@31.5,36.775 SC3.1@27.5,36.775 ; SC1.1@16.94,36.775 SC1.1@17.65,36.775 SC1.1@18.75,36.775 SC1.1@19.85,36.775 SC1.1@20.56,36.775 ; v1(17.15,25.025) C16.1@17.725,25.025 ; v1(18.875,16.789) v1(18.875,17.289) v1(18.875,17.789) C18.1@18.875,18.29 ; v1(19.857,18.1) v1(19.857,18.6) v1(19.857,19.1) C19.1@19.857,19.6 ; CN3.5@20.23,3.43 20.23,5.575 ; CN3.7@21.5,3.43 21.5,5.575 ; v1(23.75,17.321) C21.1@23.75,17.664 ; v1(24.743,36.75) v1(26.5,36.75) SC3.1@27.475,36.75 ; L3.2@25,34.425 v1(25.6,34.425) v1(26.1,34.425) ; v1(27.27,20.425) C17.1@27.27,21
  Bottom Layer w0.3: 0.55,3.308 CN1.49@2.331,3.308 ; 0.55,10.928 CN1.37@2.331,10.928 ; 0.55,14.738 CN1.31@2.331,14.738 ; 0.55,33.788 CN1.1@2.331,33.788 ; v1(4.125,21.25) 4.287,21.088 ; CN2.50@40.691,3.308 42.45,3.308 ; CN2.44@40.691,7.118 v1@42.45,7.118 ; CN2.38@40.691,10.928 42.45,10.928 ; CN2.32@40.691,14.738 42.45,14.738 ; CN2.26@40.691,18.548 v1@42.45,18.548 ; CN2.20@40.691,22.358 42.45,22.358 ; CN2.14@40.691,26.168 42.45,26.168 ; CN2.2@40.691,33.788 42.45,33.788
  Bottom Layer w0.45: v1(0.438,18.378) 0.608,18.548 CN1.25@2.331,18.548 ; v1(0.438,23.977) 0.711,23.704 2.255,23.704 CN1.17@2.331,23.628 ; v1(0.438,29.577) 0.711,29.85 2.203,29.85 CN1.7@2.331,29.978 ; CN1.49@2.343,3.32 v1(4.35,3.32) ; CN1.37@2.343,10.94 CN1.37@3.462,10.943 ; CN1.31@2.343,14.75 3.501,14.762 v1(4.101,14.762) ; CN1.25@2.343,18.56 v1(4.35,18.56) ; CN1.17@2.343,23.64 v1(4.35,23.64) ; CN1.7@2.343,29.99 v1(4.35,29.99) ; CN1.1@2.343,33.8 v1(4.35,33.8) ; CN1.37@3.463,10.943 cw(c3.463,10.643) CN1.37@3.465,10.943 ; v1(4.375,6.275) 4.802,5.848 CN1.46@6.401,5.848 ; CN1.40@6.401,9.658 v1(8.42,9.658) ; CN1.34@6.401,13.468 6.432,13.437 v1(8.42,13.437) ; CN1.28@6.413,17.29 v1(8.42,17.29) ; CN1.22@6.413,21.1 v1(8.42,21.1) ; CN1.14@6.413,26.18 v1(8.42,26.18) ; CN1.6@6.413,31.26 v1(8.42,31.26) ; v1(38.625,33.788) CN2.2@40.691,33.788 ; v1(38.684,18.548) CN2.26@40.691,18.548 ; v1(38.684,22.358) CN2.20@40.691,22.358 ; v1(38.684,26.168) CN2.14@40.691,26.168 ; v1(39,15.2) 39.521,14.883 CN2.32@40.691,14.738 ; v1(40,2.375) 40,3.163 40.145,3.308 CN2.50@40.691,3.308 ; CN2.8@40.546,29.833 CN2.8@40.691,29.978 40.836,29.833 42.282,29.833 v1(42.538,29.577)
  Bottom Layer w0.5: 4.287,21.088 CN1.22@6.401,21.088 ; v1(4.375,17) 4.653,17.278 CN1.28@6.401,17.278 ; CN1.46@6.401,5.848 8.16,5.848 v1(8.187,5.875)
  other v1: 2.04,0.447 4.84,0.447 7.64,0.447 10.44,0.447 13.24,0.447 16.04,0.447 18.839,0.447 21.639,0.447 24.439,0.447 27.239,0.447 30.039,0.447 32.839,0.447 35.638,0.447 38.438,0.447 41.238,0.447 4.836,1.39 39.312,1.5 40.625,1.5 0.438,1.579 42.538,1.579 3.375,1.625 1.4,1.924 39,2.275 41.25,2.375 3.75,2.438 4.687,2.438 42.3,2.45 8.187,2.688 8.625,3.187 13.757,3.712 29.098,4.125 0.438,4.378 42.538,4.378 13.757,4.724 16.678,4.938 20.875,5 22.125,5 23.437,5 20.875,5.813 22.125,5.813 23.437,5.813 29.713,5.813 0.438,7.178 42.538,7.178 0.438,9.978 42.538,9.978 0.438,12.778 42.538,12.778 15.275,13.254 25.578,13.281 16.138,13.493 15.282,14.279 16.138,14.501 19.7,14.501 15.282,15.2 0.438,15.578 42.538,15.578 18.875,15.752 38.625,16.063 17.15,16.34 11.5,17 21.425,17.378 38.625,17.375 22.05,17.848 21.425,17.9 42.538,18.378 21.425,18.446 11.5,18.75 38.625,19.75 38.625,21.125 0.438,21.177 42.538,21.177 21.5,21.5 23.25,21.5 25.25,21.5 22.5,22.5 24.25,22.5 23.35,23.45 21.5,23.5 25.25,23.5 8.25,23.625 42.538,23.977 22.5,24.25 24.25,24.25 32.473,24.263 31.497,24.311 9,24.875 38.687,25.063 21.5,25.25 23.25,25.25 25.25,25.25 31.516,26.2 32.473,26.2 12.187,26.688 0.438,26.777 42.538,26.777 11.5,26.875 38.687,27.063 12.812,27.125 9.5,27.25 16.243,27.769 18.749,27.937 12.812,28.062 11.5,28.125 8.25,28.375 10.25,28.375 18.749,28.486 18.098,28.536 19.399,28.536 17.448,28.786 20.049,28.786 13.563,28.875 14.625,28.875 27.025,29.375 17.446,29.404 18.096,29.404 19.519,29.404 20.169,29.404 31.5,29.5 12.395,29.769 14.341,29.768 16.243,29.769 34.114,30 8.25,30.125 10.25,30.125 19.559,30.459 11.5,30.625 18.184,30.722 25.002,31.031 10.25,31.25 21.375,31.26 23.4,31.366 19.559,31.409 18.184,31.671 12.395,31.763 14.341,31.768 16.341,31.768 11.5,31.875 31.5,31.875 4.375,32 38.597,32.105 25.584,32.276 23.4,32.326 19.702,32.358 0.438,32.377 21.381,32.375 42.538,32.377 8.25,32.625 10.25,32.625 18.338,32.619 38.613,32.959 20.044,33.255 23.4,33.286 18.635,33.532 22,33.684 12.395,33.769 14.341,33.768 16.341,33.768 26.449,33.766 20.538,34.078 23.4,34.245 27.584,34.276 29.584,34.276 19.073,34.386 1.75,34.75 4,34.75 6,34.75 8.25,34.75 10.25,34.75 33,34.75 35.25,34.75 37.25,34.75 39.5,34.75 41.5,34.75 21.183,34.789 0.438,35.177 19.636,35.164 42.538,35.177 23.4,35.205 21.785,35.537 12.408,35.776 14.339,35.776 16.339,35.776 18.339,35.776 24.75,35.776 25.584,35.776 27.584,35.776 29.584,35.776 20.295,35.862 23.4,36.164 1.75,36.25 4,36.25 6,36.25 8.25,36.25 10.25,36.25 33,36.25 35.25,36.25 37.25,36.25 39.5,36.25 41.5,36.25 22.147,36.426 28.875,36.75 14.085,36.775 22.992,36.912 24.35,37.371 20.879,37.613 0.438,37.976 42.538,37.976 1.75,38 4,38 6,38 8.25,38 10.25,38 12.25,38 14,38 16,38 17.75,38 19.25,38 23.883,38 25.5,38 27.25,38 29.25,38 31,38 33,38 35,38 37.25,38 39.25,38 41.5,38 20.879,38.573 18.073,39.125 19.224,39.125 24.05,39.25 25.15,39.25 20.879,39.533 22.221,39.533 1.75,40.25 4,40.25 6,40.25 8.25,40.25 10.25,40.25 12.25,40.25 14,40.25 16,40.25 17.75,40.25 19.25,40.25 24,40.25 25.5,40.25 27.25,40.25 29.25,40.25 31,40.25 33,40.25 35,40.25 37.25,40.25 39.25,40.25 41.5,40.25 20.879,40.492 22.221,40.492 0.438,40.776 42.538,40.776 19.625,41.125 20.879,41.452 15.375,41.5 16.625,41.5 17.75,41.5 18.75,41.5 24.25,41.5 25.25,41.5 26.375,41.5 27.625,41.5 15.375,42.25 18.75,42.25 24.25,42.25 27.625,42.25 20.879,42.411 22.221,42.411 1.75,42.5 4,42.5 6,42.5 8.25,42.5 10.25,42.5 12.25,42.5 14,42.5 29.25,42.5 31,42.5 33,42.5 35,42.5 37.25,42.5 39.25,42.5 41.5,42.5 15.375,43.25 18.75,43.25 24.25,43.25 27.625,43.25 20.879,43.371 22.221,43.371 0.438,43.576 42.538,43.576 4.75,43.75 6.75,43.75 9,43.75 11,43.75 13,43.75 29.25,44 31,44 33,44 35,44 37.25,44 41.5,44 15.375,44.25 18.75,44.25 24.25,44.25 27.625,44.25 20.879,44.331 22.221,44.331 1.75,45.25 4,45.25 5.5,45.25 7.5,45.25 9.75,45.25 11.75,45.25 13.5,45.25 15.375,45.25 18.75,45.25 24.25,45.25 27.625,45.25 20.879,45.29 22.221,45.29 29.25,45.5 31,45.5 33,45.5 35,45.5 37.25,45.5 39.25,45.5 41.5,45.5 18.75,46.25 20.879,46.25 22.221,46.25 24.25,46.25 0.67,46.288 3.47,46.288 6.27,46.288 9.069,46.288 11.869,46.288 15.325,46.3 27.675,46.3 28.668,46.288 31.468,46.288 34.268,46.288 37.068,46.288 39.868,46.288 42.328,46.288
GPIO3/BOOT0: CN1.9 R2.2 U1.10 | length 73.3
  Top Layer w0.15: v1(4.35,28.72) 4.35,26.816 5.436,25.73 5.436,20.922 3.1,18.586 3.1,10.846 3.755,10.191 4.634,10.191 v1(4.653,10.21) ; U1.10@26.125,24.85 28.909,24.85 29.117,25.058 v1(29.124,25.058) 29.172,25.058 29.76,24.47 29.76,22.412 29.649,22.301 29.649,18.682 29.768,18.564 29.768,18.307 29.77,18.305 29.77,17.286 30.175,16.882 30.175,15.295 30.06,15.18 30.06,14.452 30.2,14.313 30.2,13.199 v1(29.85,12.849) ; R2.2@33.475,24.5 v1(33.475,25.175)
  Bottom Layer w0.15: v1(4.653,10.21) 4.978,10.251 cw(c5.006,10.028) 5.006,10.253 8.5,10.253 10.398,8.355 16.486,8.355 18.207,10.076 24.403,10.076 24.553,9.926 27.021,9.926 27.439,10.344 27.439,12.042 28.284,12.887 29.813,12.887 v1(29.85,12.849) ; v1(29.124,25.058) 29.821,25.058 29.937,25.175 v1(33.475,25.175)
  Bottom Layer w0.45: CN1.9@2.343,28.72 v1(4.35,28.72)
GPIO5/SWDIO: CN1.13 R3.2 U1.1 | length 60.5
  Top Layer w0.15: v1(4.35,9) 2.8,10.55 2.8,18.71 5.136,21.046 5.136,25.394 v1(4.35,26.18) ; U1.1@26.125,21.25 26.125,20.099 26.363,19.861 26.363,19.363 27.96,17.765 27.96,14.672 28.412,14.221 28.412,12.447 v1(28.446,12.413)
  Top Layer w0.3: v1(18.125,9.326) 18.125,10.225 18.3,10.4 R3.2@18.95,10.4
  Bottom Layer w0.15: v1(4.35,9) 8.775,9 9.72,8.055 16.854,8.055 v1(18.125,9.326) 18.575,9.776 21.544,9.776 21.694,9.626 28.038,9.626 28.446,10.035 v1(28.446,12.413)
  Bottom Layer w0.45: CN1.13@2.343,26.18 v1(4.35,26.18)
GPIO6/SWCLK: CN1.15 R4.2 U1.2 | length 61.8
  Top Layer w0.15: v1(4.287,7.7) 2.5,9.487 2.5,18.834 4.836,21.171 4.836,24.424 v1(4.35,24.91) ; U1.2@26.125,21.65 26.564,21.65 26.614,21.6 26.779,21.435 26.779,19.371 28.26,17.89 28.26,14.797 28.734,14.323 28.734,12.827 v1(29.124,12.437)
  Top Layer w0.3: R4.2@20.225,10.4 20.231,10.406 20.8,10.406 21.17,10.035 v1(21.17,9.326)
  Bottom Layer w0.15: v1(4.287,7.7) 4.299,7.712 cw(c4.405,7.605) 4.405,7.755 15.727,7.755 16.98,7.755 17.44,8.215 18.239,8.215 19.35,9.326 v1(21.17,9.326) 28.272,9.326 28.776,9.829 28.776,11.686 29.124,12.035 v1(29.124,12.437)
  Bottom Layer w0.45: CN1.15@2.343,24.91 v1(4.35,24.91)
GPIO11: CN1.24 U1.46 | length 39
  Top Layer w0.15: v1(8.42,19.83) 8.42,19.196 9.371,18.246 9.371,12.024 v1(9.7,11.695) ; U1.46@24.75,20.675 24.75,20.201 25.463,19.489 25.463,18.99 27.016,17.437 cw(c26.91,17.331) 27.06,17.331 27.06,14.768 26.935,14.643 v1(26.935,13.866)
  Bottom Layer w0.15: v1(9.7,11.695) 9.8,11.594 11.255,11.594 11.636,11.213 11.636,10.345 12.101,9.88 15.889,9.88 17.604,11.594 24.293,11.594 24.443,11.743 25.443,11.743 26.534,12.834 ccw(c26.428,12.94) 26.568,12.887 26.935,13.254 v1(26.935,13.866)
  Bottom Layer w0.45: CN1.24@6.413,19.83 v1(8.42,19.83)
GPIO12: CN1.26 U1.47 | length 38.3
  Top Layer w0.15: v1(8.42,18.56) 8.42,17.926 9.05,17.296 v1(9.05,11.688) ; U1.47@25.15,20.675 25.15,20.226 25.763,19.613 25.763,19.114 26.854,18.023 27.316,17.561 cw(c27.21,17.455) 27.36,17.455 27.36,14.293 27.406,14.248 v1(27.406,13.493)
  Bottom Layer w0.15: v1(9.05,11.688) 9.1,11.638 9.1,11.443 9.962,10.582 10.634,10.582 11.636,9.58 16.013,9.58 17.728,11.294 24.418,11.294 24.567,11.443 25.506,11.443 ccw(c25.506,11.593) 25.611,11.487 27.406,13.281 v1(27.406,13.493)
  Bottom Layer w0.45: CN1.26@6.413,18.56 v1(8.42,18.56)
GPIO14: CN1.29 U1.5 | length 45.2
  Top Layer w0.15: U1.5@26.125,22.85 28.378,22.85 28.749,22.478 28.749,18.249 28.868,18.131 28.868,15.25 v1(29.174,14.943)
  Bottom Layer w0.15: v1(4.35,16.02) 4.653,15.717 4.653,11.778 4.836,11.594 8.42,11.594 9.733,10.282 10.51,10.282 11.512,9.28 16.138,9.28 16.678,9.82 ; 16.689,9.831 17.852,10.994 24.542,10.994 24.691,11.143 25.692,11.143 28.032,13.483 28.272,13.724 28.765,13.724 29.16,14.119 29.16,14.93 v1(29.174,14.943)
  Bottom Layer w0.45: CN1.29@2.343,16.02 v1(4.35,16.02)
GPIO15/OSC32_IN: CN1.33 SB3.2 | length 86.2
  Top Layer w0.15: v1(4.101,13.437) 5.187,13.437 5.85,12.774 v1(5.85,1.39) ; v1(28.86,1.375) 29.531,1.375 29.681,1.225 36.912,1.225 41.5,5.813 41.5,30.227 40.452,31.275 35.338,31.275 35.25,31.363 35.25,31.916 34.8,32.366 v1(34.8,32.747)
  Bottom Layer w0.15: v1(5.85,1.39) 5.865,1.375 v1(28.86,1.375) v1@28.873,1.375 ; SB3.2@34.1,32.747 SB3.2@34.175,32.747 v1(34.8,32.747)
  Bottom Layer w0.45: CN1.33@2.343,13.48 3.501,13.437 v1(4.101,13.437)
